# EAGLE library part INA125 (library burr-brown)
Instrumentation Amplifier with Precision Voltage Reference
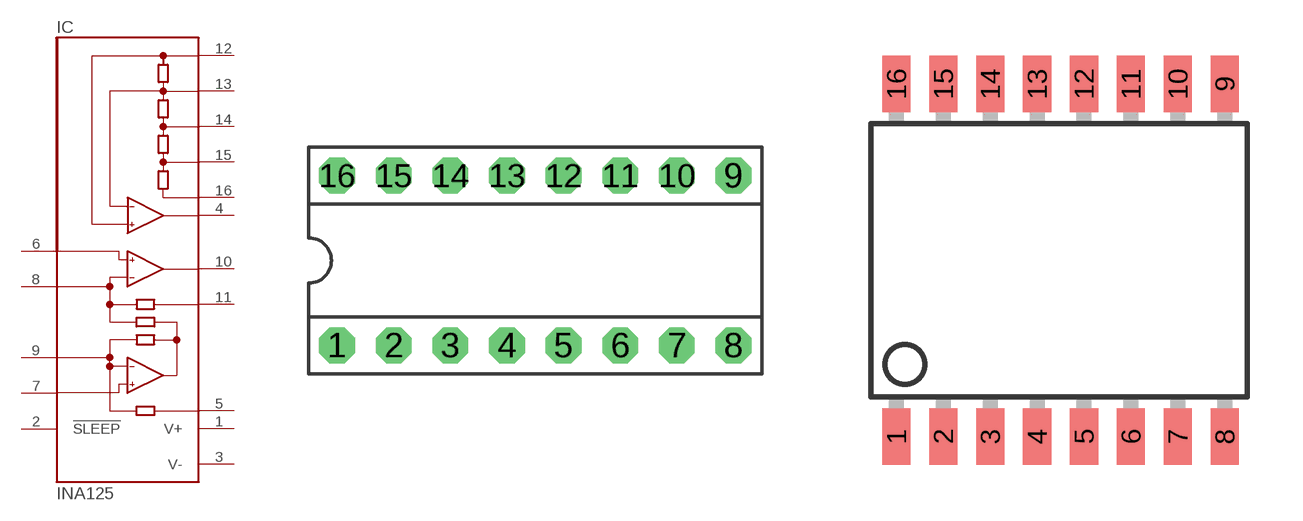
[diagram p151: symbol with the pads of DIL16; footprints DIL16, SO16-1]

Designator prefix IC

## INA125P (MF: TEXAS INSTRUMENT CONNECTORS; MPN: INA125P; OC_FARNELL: 1459461; OC_NEWARK: 35C1726)  [DIL16]
1  V+  pwr
2  !SLEEP  in
3  V-  pwr
4  REFOUT  out
5  REF  pas
6  +IN  in
7  -IN  in
8  RG  pas
9  RG  pas
10  OUT  out
11  SENSE  pas
12  REFCOM  pas
13  REFBG  out
14  REF2.5  out
15  REF5  out
16  REF10  out

## INA125U (MF: TEXAS INSTRUMENT CONNECTORS; MPN: INA125U; OC_FARNELL: 1304375; OC_NEWARK: 80K5901)  [SO16-1]
Pads as for DIL16

## Footprint DIL16 (pad centres in mm)
Dual In Line
drill 0.813 pad 1.6 octagon: 1 -8.89,-3.81; 2 -6.35,-3.81; 3 -3.81,-3.81; 4 -1.27,-3.81; 5 1.27,-3.81; 6 3.81,-3.81; 7 6.35,-3.81; 8 8.89,-3.81; 9 8.89,3.81; 10 6.35,3.81; 11 3.81,3.81; 12 1.27,3.81; 13 -1.27,3.81; 14 -3.81,3.81; 15 -6.35,3.81; 16 -8.89,3.81

## Footprint SO16-1 (pad centres in mm)
Small Outline Package
smd 0.762 x 1.524: 1 -4.445,-4.775; 2 -3.175,-4.775; 3 -1.905,-4.775; 4 -0.635,-4.775; 5 0.635,-4.775; 6 1.905,-4.775; 7 3.175,-4.775; 8 4.445,-4.775; 9 4.445,4.775; 10 3.175,4.775; 11 1.905,4.775; 12 0.635,4.775; 13 -0.635,4.775; 14 -1.905,4.775; 15 -3.175,4.775; 16 -4.445,4.775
